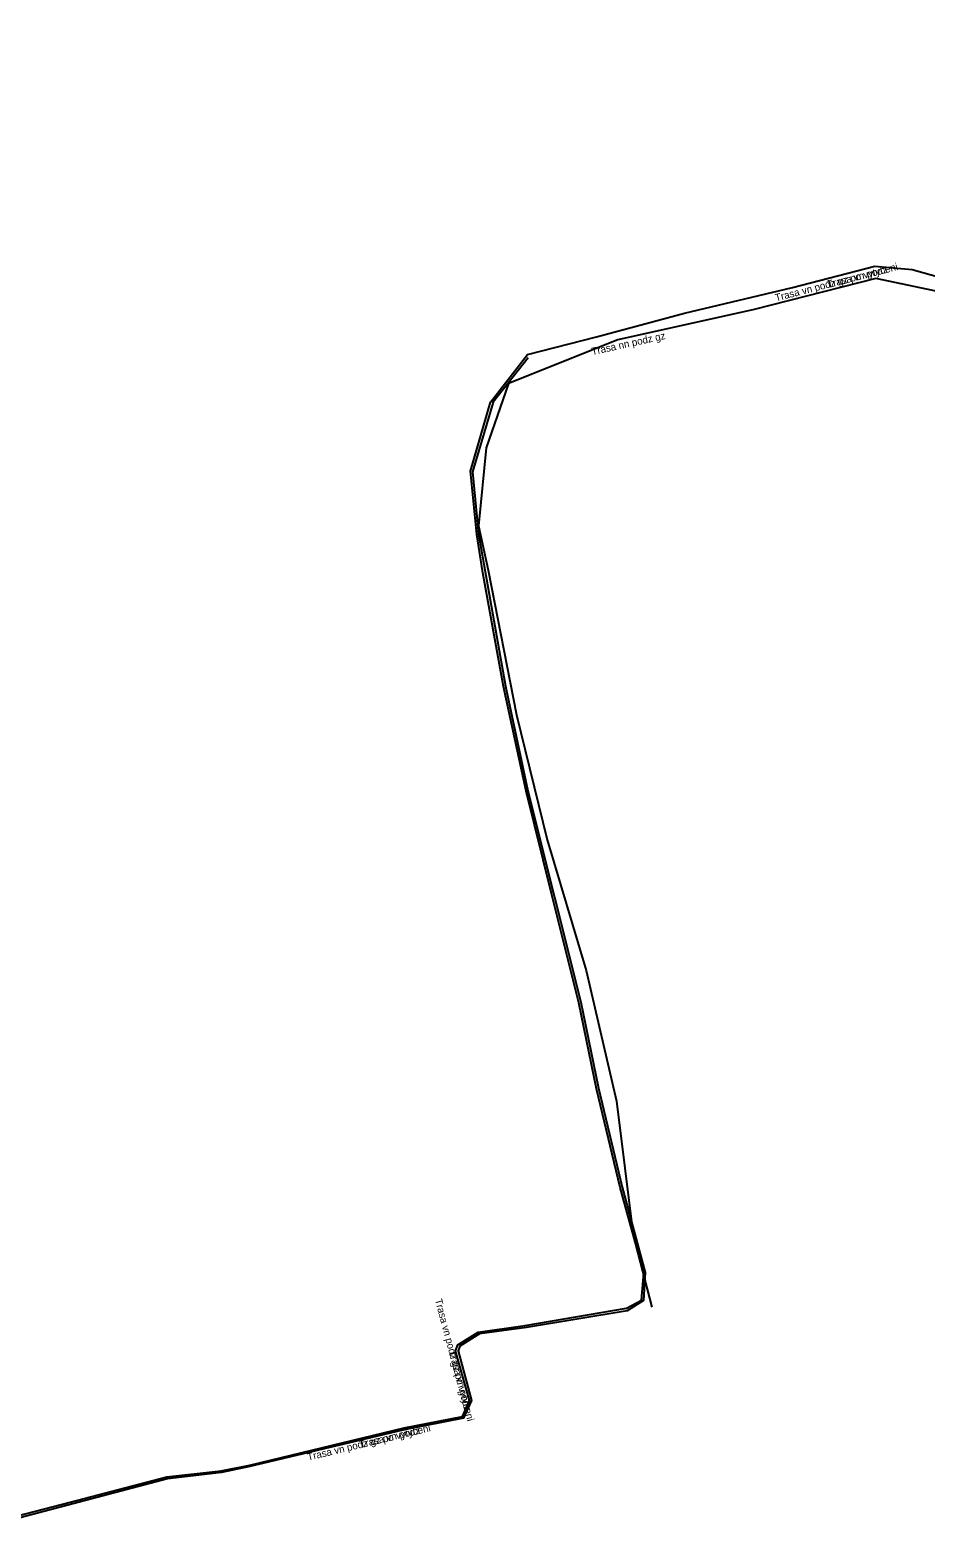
# Model space of a CAD drawing. Extents: x -473162 to -472629, y -1107202 to -1106680.
# Drawn here: x -472854.5 to -472793.2, y -1107191.2 to -1107087.9 of the extents above; entities that cross this region are included whole.
import ezdxf

# ---------------------------------------------------------------- set-up
doc = ezdxf.new("R2010")
doc.units = 0
for name, color, linetype in [('Popiskový text - Ostatní atributy Trasy', 7, 'Continuous'), ('Spojnice NN', 7, 'Continuous'), ('Spojnice VN', 7, 'Continuous')]:
    doc.layers.add(name, color=color, linetype=linetype)

msp = doc.modelspace()

# ---------------------------------------------------------------- linework, layer by layer
at = {"layer": 'Spojnice NN'}
msp.add_lwpolyline([(-472744.5, -1107087.87), (-472748.86, -1107088.93), (-472754.05, -1107090.09), (-472765.51, -1107093.03), (-472768.58, -1107093.84), (-472770.57, -1107094.86), (-472773.84, -1107102.53), (-472779.8, -1107104.6), (-472786.27, -1107106.09), (-472792.58, -1107105.72), (-472796.6, -1107104.88), (-472804.93, -1107107.02), (-472814.28, -1107109.09), (-472821.76, -1107112.09), (-472823.28, -1107116.48), (-472823.82, -1107121.84), (-472823.15, -1107124.88), (-472821.22, -1107134.78), (-472819.12, -1107143.34), (-472816.44, -1107152.3), (-472814.37, -1107161.26), (-472813.21, -1107170.44), (-472811.95, -1107175.37)], dxfattribs=at)
at = {"layer": 'Spojnice VN'}
for points in [[(-472820.47, -1107110.09), (-472815.74, -1107108.88), (-472809.7, -1107107.26), (-472802.3, -1107105.5), (-472796.66, -1107104.03), (-472794.1, -1107104.27), (-472792.08, -1107104.85), (-472786.5, -1107105.23), (-472779.86, -1107103.64), (-472773.74, -1107100.64)], [(-472820.47, -1107110.09), (-472815.74, -1107108.88), (-472809.7, -1107107.26), (-472802.3, -1107105.5), (-472796.66, -1107104.03), (-472794.1, -1107104.27), (-472792.08, -1107104.85), (-472786.5, -1107105.23), (-472779.86, -1107103.64), (-472773.74, -1107100.64)], [(-472860.45, -1107190.97), (-472851.8, -1107188.73), (-472845.17, -1107186.98), (-472841.44, -1107186.59), (-472839.49, -1107186.19), (-472828.91, -1107183.63), (-472824.92, -1107182.85), (-472824.43, -1107181.76), (-472825.39, -1107178.36), (-472825.23, -1107177.94), (-472823.83, -1107177.07), (-472820.61, -1107176.61), (-472813.68, -1107175.44), (-472812.64, -1107174.88), (-472812.48, -1107173.04), (-472814.1, -1107167.17), (-472815.73, -1107160.4), (-472816.95, -1107154.52), (-472818.82, -1107147.02), (-472820.54, -1107140.01), (-472822.11, -1107132.83), (-472823.51, -1107125.06), (-472823.92, -1107122.43), (-472824.36, -1107118.09), (-472823, -1107113.35), (-472820.47, -1107110.09)], [(-472860.45, -1107190.97), (-472851.8, -1107188.73), (-472845.17, -1107186.98), (-472841.44, -1107186.59), (-472839.49, -1107186.19), (-472828.91, -1107183.63), (-472824.92, -1107182.85), (-472824.43, -1107181.76), (-472825.39, -1107178.36), (-472825.23, -1107177.94), (-472823.83, -1107177.07), (-472820.61, -1107176.61), (-472813.68, -1107175.44), (-472812.64, -1107174.88), (-472812.48, -1107173.04), (-472814.1, -1107167.17), (-472815.73, -1107160.4), (-472816.95, -1107154.52), (-472818.82, -1107147.02), (-472820.54, -1107140.01), (-472822.11, -1107132.83), (-472823.51, -1107125.06), (-472823.92, -1107122.43), (-472824.36, -1107118.09), (-472823, -1107113.35), (-472820.47, -1107110.09)], [(-472820.41, -1107110.32), (-472822.8, -1107113.36), (-472824.22, -1107118.13), (-472823.82, -1107122.41), (-472821.97, -1107132.81), (-472820.44, -1107139.99), (-472816.81, -1107154.47), (-472815.59, -1107160.36), (-472813.97, -1107167.14), (-472812.39, -1107172.99), (-472812.52, -1107174.91), (-472813.64, -1107175.61), (-472820.52, -1107176.76), (-472823.75, -1107177.19), (-472825.1, -1107178.04), (-472825.2, -1107178.35), (-472824.29, -1107181.76), (-472824.84, -1107182.97), (-472828.9, -1107183.78), (-472839.49, -1107186.28), (-472841.42, -1107186.69), (-472845.13, -1107187.13), (-472860.44, -1107191.17)], [(-472820.41, -1107110.32), (-472822.8, -1107113.36), (-472824.22, -1107118.13), (-472823.82, -1107122.41), (-472821.97, -1107132.81), (-472820.44, -1107139.99), (-472816.81, -1107154.47), (-472815.59, -1107160.36), (-472813.97, -1107167.14), (-472812.39, -1107172.99), (-472812.52, -1107174.91), (-472813.64, -1107175.61), (-472820.52, -1107176.76), (-472823.75, -1107177.19), (-472825.1, -1107178.04), (-472825.2, -1107178.35), (-472824.29, -1107181.76), (-472824.84, -1107182.97), (-472828.9, -1107183.78), (-472839.49, -1107186.28), (-472841.42, -1107186.69), (-472845.13, -1107187.13), (-472860.44, -1107191.17)]]:
    msp.add_lwpolyline(points, dxfattribs=at)

# ---------------------------------------------------------------- texts
at = {"layer": 'Popiskový text - Ostatní atributy Trasy'}
for s, rotation, p in [('Trasa vn podz gz po vytyceni', 14.501, (-472803.43, -1107106.46)), ('Trasa vn podz', 14.501, (-472799.86, -1107105.54)), ('Trasa nn podz gz', 12.4834, (-472816.02, -1107110.14)), ('Trasa vn podz gz po vytyceni', 284.9419, (-472826.81, -1107174.86)), ('Trasa vn podz', 284.9419, (-472825.86, -1107178.42)), ('Trasa vn podz gz po vytyceni', 13.5766, (-472835.48, -1107185.89)), ('Trasa vn podz', 13.5766, (-472831.9, -1107185.02))]:
    msp.add_text(s, height=0.5, rotation=rotation, dxfattribs=at).set_placement(p)

doc.saveas('drawing.dxf')
